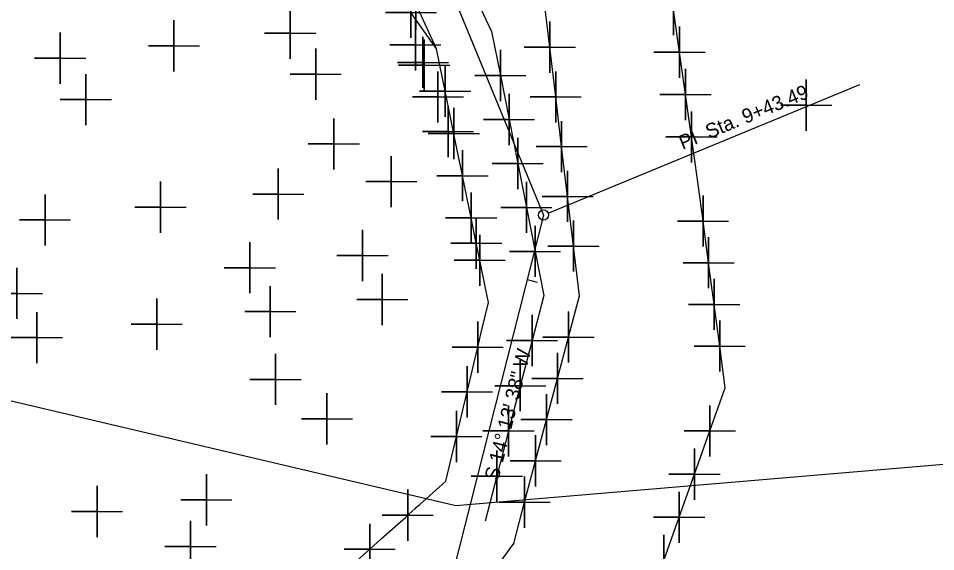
# Model space of a CAD drawing. Extents: x 2260968 to 2264340, y 653057 to 655850.
# Drawn here: x 2261691.8 to 2261781.6, y 654817.2 to 654869.4 of the extents above; entities that cross this region are included whole.
import ezdxf

# ---------------------------------------------------------------- set-up
doc = ezdxf.new("R2010")
doc.units = 0
for name, color, linetype in [('CL_X_Construction', 7, 'Continuous'), ('Default', 7, 'Continuous'), ('GE_X_CL_10', 7, 'Continuous'), ('GK_Patterns2', 7, 'Continuous')]:
    doc.layers.add(name, color=color, linetype=linetype)

msp = doc.modelspace()

# ---------------------------------------------------------------- linework, layer by layer
at = {"layer": 'CL_X_Construction'}
for p, q in [((2261716.474, 654914.987), (2261743.195, 654850.138)), ((2261716.474, 654914.987), (2261743.195, 654850.138)), ((2261743.195, 654850.138), (2261734.002, 654813.881)), ((2261743.195, 654850.138), (2261734.002, 654813.881))]:
    msp.add_line(p, q, dxfattribs=at)
at = {"layer": 'Default'}
for points in [[(2261730.718, 654870.778), (2261730.718, 654873.278), (2261730.718, 654870.778), (2261728.218, 654870.778), (2261730.718, 654870.778), (2261730.718, 654868.278), (2261730.718, 654870.778), (2261733.218, 654870.778)], [(2261730.233, 654869.95), (2261730.233, 654872.45), (2261730.233, 654869.95), (2261727.733, 654869.95), (2261730.233, 654869.95), (2261730.233, 654867.45), (2261730.233, 654869.95), (2261732.733, 654869.95)], [(2261736.009, 654872.552), (2261738.125, 654868.075), (2261738.975, 654863.776), (2261739.825, 654859.477), (2261740.674, 654855.178), (2261741.524, 654850.879), (2261742.374, 654846.58), (2261743.224, 654842.28), (2261742.076, 654837.864), (2261740.928, 654833.448), (2261739.779, 654829.032), (2261738.631, 654824.615), (2261737.483, 654820.199)], [(2261755.909, 654870.203), (2261755.909, 654872.703), (2261755.909, 654870.203), (2261753.409, 654870.203), (2261755.909, 654870.203), (2261755.909, 654867.703), (2261755.909, 654870.203), (2261758.409, 654870.203)], [(2261737.636, 654814.385), (2261740.28, 654818.033), (2261741.351, 654822.068), (2261742.422, 654826.102), (2261743.493, 654830.137), (2261744.564, 654834.171), (2261745.636, 654838.206), (2261746.707, 654842.24), (2261746.128, 654847.1), (2261745.55, 654851.96), (2261744.971, 654856.82), (2261744.393, 654861.68), (2261743.815, 654866.539), (2261743.236, 654871.399)], [(2261718.42, 654867.92), (2261718.42, 654870.42), (2261718.42, 654867.92), (2261715.92, 654867.92), (2261718.42, 654867.92), (2261718.42, 654865.42), (2261718.42, 654867.92), (2261720.92, 654867.92)], [(2261722.48, 654814.139), (2261726.2, 654817.465), (2261727.325, 654818.471), (2261729.197, 654820.144), (2261729.687, 654820.583), (2261729.919, 654820.79), (2261730.017, 654820.878), (2261730.608, 654821.406), (2261730.646, 654821.44), (2261730.67, 654821.462), (2261730.788, 654821.568), (2261731.092, 654821.839), (2261733.638, 654824.116), (2261734.681, 654828.482), (2261735.724, 654832.848), (2261736.767, 654837.214), (2261737.113, 654838.664), (2261737.809, 654841.58), (2261737.521, 654842.99), (2261736.963, 654845.713), (2261736.62, 654847.39), (2261736.62, 654847.39), (2261736.62, 654847.39), (2261736.117, 654849.846), (2261735.271, 654853.979), (2261735.236, 654854.15), (2261734.474, 654857.872), (2261734.425, 654858.112), (2261733.579, 654862.245), (2261732.733, 654866.378), (2261730.718, 654870.778)], [(2261754.959, 654816.366), (2261756.461, 654820.587), (2261757.964, 654824.809), (2261759.466, 654829.03), (2261760.969, 654833.252), (2261760.428, 654837.326), (2261759.888, 654841.4), (2261759.347, 654845.474), (2261758.806, 654849.548), (2261758.266, 654853.621), (2261757.677, 654857.767), (2261757.087, 654861.912), (2261756.498, 654866.057), (2261755.909, 654870.203)], [(2261730.668, 654866.763), (2261730.668, 654869.263), (2261730.668, 654866.763), (2261728.168, 654866.763), (2261730.668, 654866.763), (2261730.668, 654864.263), (2261730.668, 654866.763), (2261733.168, 654866.763)], [(2261732.733, 654866.378), (2261730.233, 654869.95)], [(2261707.05, 654866.68), (2261707.05, 654869.18), (2261707.05, 654866.68), (2261704.55, 654866.68), (2261707.05, 654866.68), (2261707.05, 654864.18), (2261707.05, 654866.68), (2261709.55, 654866.68)], [(2261743.815, 654866.539), (2261743.815, 654869.039), (2261743.815, 654866.539), (2261741.315, 654866.539), (2261743.815, 654866.539), (2261743.815, 654864.039), (2261743.815, 654866.539), (2261746.315, 654866.539)], [(2261756.498, 654866.057), (2261756.498, 654868.557), (2261756.498, 654866.057), (2261753.998, 654866.057), (2261756.498, 654866.057), (2261756.498, 654863.557), (2261756.498, 654866.057), (2261758.998, 654866.057)], [(2261695.93, 654865.47), (2261695.93, 654867.97), (2261695.93, 654865.47), (2261693.43, 654865.47), (2261695.93, 654865.47), (2261695.93, 654862.97), (2261695.93, 654865.47), (2261698.43, 654865.47)], [(2261731.408, 654865.058), (2261731.408, 654867.558), (2261731.408, 654865.058), (2261728.908, 654865.058), (2261731.408, 654865.058), (2261731.408, 654862.558), (2261731.408, 654865.058), (2261733.908, 654865.058)], [(2261731.522, 654864.797), (2261731.522, 654867.297), (2261731.522, 654864.797), (2261729.022, 654864.797), (2261731.522, 654864.797), (2261731.522, 654862.297), (2261731.522, 654864.797), (2261734.022, 654864.797)], [(2261720.92, 654863.91), (2261720.92, 654866.41), (2261720.92, 654863.91), (2261718.42, 654863.91), (2261720.92, 654863.91), (2261720.92, 654861.41), (2261720.92, 654863.91), (2261723.42, 654863.91)], [(2261738.975, 654863.776), (2261738.975, 654866.276), (2261738.975, 654863.776), (2261736.475, 654863.776), (2261738.975, 654863.776), (2261738.975, 654861.276), (2261738.975, 654863.776), (2261741.475, 654863.776)], [(2261733.579, 654862.245), (2261733.579, 654864.745), (2261733.579, 654862.245), (2261731.079, 654862.245), (2261733.579, 654862.245), (2261733.579, 654859.745), (2261733.579, 654862.245), (2261736.079, 654862.245)], [(2261698.44, 654861.42), (2261698.44, 654863.92), (2261698.44, 654861.42), (2261695.94, 654861.42), (2261698.44, 654861.42), (2261698.44, 654858.92), (2261698.44, 654861.42), (2261700.94, 654861.42)], [(2261732.877, 654861.677), (2261732.877, 654864.177), (2261732.877, 654861.677), (2261730.377, 654861.677), (2261732.877, 654861.677), (2261732.877, 654859.177), (2261732.877, 654861.677), (2261735.377, 654861.677)], [(2261744.393, 654861.68), (2261744.393, 654864.18), (2261744.393, 654861.68), (2261741.893, 654861.68), (2261744.393, 654861.68), (2261744.393, 654859.18), (2261744.393, 654861.68), (2261746.893, 654861.68)], [(2261757.087, 654861.912), (2261757.087, 654864.412), (2261757.087, 654861.912), (2261754.587, 654861.912), (2261757.087, 654861.912), (2261757.087, 654859.412), (2261757.087, 654861.912), (2261759.587, 654861.912)], [(2261768.898, 654860.875), (2261768.898, 654863.375), (2261768.898, 654860.875), (2261766.398, 654860.875), (2261768.898, 654860.875), (2261768.898, 654858.375), (2261768.898, 654860.875), (2261771.398, 654860.875)], [(2261739.825, 654859.477), (2261739.825, 654861.977), (2261739.825, 654859.477), (2261737.325, 654859.477), (2261739.825, 654859.477), (2261739.825, 654856.977), (2261739.825, 654859.477), (2261742.325, 654859.477)], [(2261733.86, 654858.29), (2261733.86, 654860.79), (2261733.86, 654858.29), (2261731.36, 654858.29), (2261733.86, 654858.29), (2261733.86, 654855.79), (2261733.86, 654858.29), (2261736.36, 654858.29)], [(2261734.425, 654858.112), (2261734.425, 654860.612), (2261734.425, 654858.112), (2261731.925, 654858.112), (2261734.425, 654858.112), (2261734.425, 654855.612), (2261734.425, 654858.112), (2261736.925, 654858.112)], [(2261757.677, 654857.767), (2261757.677, 654860.267), (2261757.677, 654857.767), (2261755.177, 654857.767), (2261757.677, 654857.767), (2261757.677, 654855.267), (2261757.677, 654857.767), (2261760.177, 654857.767)], [(2261722.69, 654857.08), (2261722.69, 654859.58), (2261722.69, 654857.08), (2261720.19, 654857.08), (2261722.69, 654857.08), (2261722.69, 654854.58), (2261722.69, 654857.08), (2261725.19, 654857.08)], [(2261744.971, 654856.82), (2261744.971, 654859.32), (2261744.971, 654856.82), (2261742.471, 654856.82), (2261744.971, 654856.82), (2261744.971, 654854.32), (2261744.971, 654856.82), (2261747.471, 654856.82)], [(2261740.674, 654855.178), (2261740.674, 654857.678), (2261740.674, 654855.178), (2261738.174, 654855.178), (2261740.674, 654855.178), (2261740.674, 654852.678), (2261740.674, 654855.178), (2261743.174, 654855.178)], [(2261728.31, 654853.4), (2261728.31, 654855.9), (2261728.31, 654853.4), (2261725.81, 654853.4), (2261728.31, 654853.4), (2261728.31, 654850.9), (2261728.31, 654853.4), (2261730.81, 654853.4)], [(2261735.271, 654853.979), (2261735.271, 654856.479), (2261735.271, 654853.979), (2261732.771, 654853.979), (2261735.271, 654853.979), (2261735.271, 654851.479), (2261735.271, 654853.979), (2261737.771, 654853.979)], [(2261717.26, 654852.19), (2261717.26, 654854.69), (2261717.26, 654852.19), (2261714.76, 654852.19), (2261717.26, 654852.19), (2261717.26, 654849.69), (2261717.26, 654852.19), (2261719.76, 654852.19)], [(2261745.55, 654851.96), (2261745.55, 654854.46), (2261745.55, 654851.96), (2261743.05, 654851.96), (2261745.55, 654851.96), (2261745.55, 654849.46), (2261745.55, 654851.96), (2261748.05, 654851.96)], [(2261705.74, 654850.9), (2261705.74, 654853.4), (2261705.74, 654850.9), (2261703.24, 654850.9), (2261705.74, 654850.9), (2261705.74, 654848.4), (2261705.74, 654850.9), (2261708.24, 654850.9)], [(2261741.524, 654850.879), (2261741.524, 654853.379), (2261741.524, 654850.879), (2261739.024, 654850.879), (2261741.524, 654850.879), (2261741.524, 654848.379), (2261741.524, 654850.879), (2261744.024, 654850.879)], [(2261694.45, 654849.65), (2261694.45, 654852.15), (2261694.45, 654849.65), (2261691.95, 654849.65), (2261694.45, 654849.65), (2261694.45, 654847.15), (2261694.45, 654849.65), (2261696.95, 654849.65)], [(2261736.117, 654849.846), (2261736.117, 654852.346), (2261736.117, 654849.846), (2261733.617, 654849.846), (2261736.117, 654849.846), (2261736.117, 654847.346), (2261736.117, 654849.846), (2261738.617, 654849.846)], [(2261758.806, 654849.548), (2261758.806, 654852.048), (2261758.806, 654849.548), (2261756.306, 654849.548), (2261758.806, 654849.548), (2261758.806, 654847.048), (2261758.806, 654849.548), (2261761.306, 654849.548)], [(2261736.62, 654847.39), (2261736.62, 654849.89), (2261736.62, 654847.39), (2261734.12, 654847.39), (2261736.62, 654847.39), (2261736.62, 654844.89), (2261736.62, 654847.39), (2261739.12, 654847.39)], [(2261746.128, 654847.1), (2261746.128, 654849.6), (2261746.128, 654847.1), (2261743.628, 654847.1), (2261746.128, 654847.1), (2261746.128, 654844.6), (2261746.128, 654847.1), (2261748.628, 654847.1)], [(2261725.5, 654846.18), (2261725.5, 654848.68), (2261725.5, 654846.18), (2261723, 654846.18), (2261725.5, 654846.18), (2261725.5, 654843.68), (2261725.5, 654846.18), (2261728, 654846.18)], [(2261742.374, 654846.58), (2261742.374, 654849.08), (2261742.374, 654846.58), (2261739.874, 654846.58), (2261742.374, 654846.58), (2261742.374, 654844.08), (2261742.374, 654846.58), (2261744.874, 654846.58)], [(2261736.963, 654845.713), (2261736.963, 654848.213), (2261736.963, 654845.713), (2261734.463, 654845.713), (2261736.963, 654845.713), (2261736.963, 654843.213), (2261736.963, 654845.713), (2261739.463, 654845.713)], [(2261759.347, 654845.474), (2261759.347, 654847.974), (2261759.347, 654845.474), (2261756.847, 654845.474), (2261759.347, 654845.474), (2261759.347, 654842.974), (2261759.347, 654845.474), (2261761.847, 654845.474)], [(2261714.48, 654844.99), (2261714.48, 654847.49), (2261714.48, 654844.99), (2261711.98, 654844.99), (2261714.48, 654844.99), (2261714.48, 654842.49), (2261714.48, 654844.99), (2261716.98, 654844.99)], [(2261691.69, 654842.48), (2261691.69, 654844.98), (2261691.69, 654842.48), (2261689.19, 654842.48), (2261691.69, 654842.48), (2261691.69, 654839.98), (2261691.69, 654842.48), (2261694.19, 654842.48)], [(2261727.43, 654841.88), (2261727.43, 654844.38), (2261727.43, 654841.88), (2261724.93, 654841.88), (2261727.43, 654841.88), (2261727.43, 654839.38), (2261727.43, 654841.88), (2261729.93, 654841.88)], [(2261716.47, 654840.69), (2261716.47, 654843.19), (2261716.47, 654840.69), (2261713.97, 654840.69), (2261716.47, 654840.69), (2261716.47, 654838.19), (2261716.47, 654840.69), (2261718.97, 654840.69)], [(2261759.888, 654841.4), (2261759.888, 654843.9), (2261759.888, 654841.4), (2261757.388, 654841.4), (2261759.888, 654841.4), (2261759.888, 654838.9), (2261759.888, 654841.4), (2261762.388, 654841.4)], [(2261705.37, 654839.47), (2261705.37, 654841.97), (2261705.37, 654839.47), (2261702.87, 654839.47), (2261705.37, 654839.47), (2261705.37, 654836.97), (2261705.37, 654839.47), (2261707.87, 654839.47)], [(2261693.64, 654838.15), (2261693.64, 654840.65), (2261693.64, 654838.15), (2261691.14, 654838.15), (2261693.64, 654838.15), (2261693.64, 654835.65), (2261693.64, 654838.15), (2261696.14, 654838.15)], [(2261745.636, 654838.206), (2261745.636, 654840.706), (2261745.636, 654838.206), (2261743.136, 654838.206), (2261745.636, 654838.206), (2261745.636, 654835.706), (2261745.636, 654838.206), (2261748.136, 654838.206)], [(2261736.767, 654837.214), (2261736.767, 654839.714), (2261736.767, 654837.214), (2261734.267, 654837.214), (2261736.767, 654837.214), (2261736.767, 654834.714), (2261736.767, 654837.214), (2261739.267, 654837.214)], [(2261742.076, 654837.864), (2261742.076, 654840.364), (2261742.076, 654837.864), (2261739.576, 654837.864), (2261742.076, 654837.864), (2261742.076, 654835.364), (2261742.076, 654837.864), (2261744.576, 654837.864)], [(2261760.428, 654837.326), (2261760.428, 654839.826), (2261760.428, 654837.326), (2261757.928, 654837.326), (2261760.428, 654837.326), (2261760.428, 654834.826), (2261760.428, 654837.326), (2261762.928, 654837.326)], [(2261716.99, 654834.07), (2261716.99, 654836.57), (2261716.99, 654834.07), (2261714.49, 654834.07), (2261716.99, 654834.07), (2261716.99, 654831.57), (2261716.99, 654834.07), (2261719.49, 654834.07)], [(2261744.564, 654834.171), (2261744.564, 654836.671), (2261744.564, 654834.171), (2261742.064, 654834.171), (2261744.564, 654834.171), (2261744.564, 654831.671), (2261744.564, 654834.171), (2261747.064, 654834.171)], [(2261735.724, 654832.848), (2261735.724, 654835.348), (2261735.724, 654832.848), (2261733.224, 654832.848), (2261735.724, 654832.848), (2261735.724, 654830.348), (2261735.724, 654832.848), (2261738.224, 654832.848)], [(2261740.928, 654833.448), (2261740.928, 654835.948), (2261740.928, 654833.448), (2261738.428, 654833.448), (2261740.928, 654833.448), (2261740.928, 654830.948), (2261740.928, 654833.448), (2261743.428, 654833.448)], [(2261722.02, 654830.21), (2261722.02, 654832.71), (2261722.02, 654830.21), (2261719.52, 654830.21), (2261722.02, 654830.21), (2261722.02, 654827.71), (2261722.02, 654830.21), (2261724.52, 654830.21)], [(2261743.493, 654830.137), (2261743.493, 654832.637), (2261743.493, 654830.137), (2261740.993, 654830.137), (2261743.493, 654830.137), (2261743.493, 654827.637), (2261743.493, 654830.137), (2261745.993, 654830.137)], [(2261739.779, 654829.032), (2261739.779, 654831.532), (2261739.779, 654829.032), (2261737.279, 654829.032), (2261739.779, 654829.032), (2261739.779, 654826.532), (2261739.779, 654829.032), (2261742.279, 654829.032)], [(2261759.466, 654829.03), (2261759.466, 654831.53), (2261759.466, 654829.03), (2261756.966, 654829.03), (2261759.466, 654829.03), (2261759.466, 654826.53), (2261759.466, 654829.03), (2261761.966, 654829.03)], [(2261734.681, 654828.482), (2261734.681, 654830.982), (2261734.681, 654828.482), (2261732.181, 654828.482), (2261734.681, 654828.482), (2261734.681, 654825.982), (2261734.681, 654828.482), (2261737.181, 654828.482)], [(2261742.422, 654826.102), (2261742.422, 654828.602), (2261742.422, 654826.102), (2261739.922, 654826.102), (2261742.422, 654826.102), (2261742.422, 654823.602), (2261742.422, 654826.102), (2261744.922, 654826.102)], [(2261738.631, 654824.615), (2261738.631, 654827.115), (2261738.631, 654824.615), (2261736.131, 654824.615), (2261738.631, 654824.615), (2261738.631, 654822.115), (2261738.631, 654824.615), (2261741.131, 654824.615)], [(2261757.964, 654824.809), (2261757.964, 654827.309), (2261757.964, 654824.809), (2261755.464, 654824.809), (2261757.964, 654824.809), (2261757.964, 654822.309), (2261757.964, 654824.809), (2261760.464, 654824.809)], [(2261710.23, 654822.29), (2261710.23, 654824.79), (2261710.23, 654822.29), (2261707.73, 654822.29), (2261710.23, 654822.29), (2261710.23, 654819.79), (2261710.23, 654822.29), (2261712.73, 654822.29)], [(2261741.351, 654822.068), (2261741.351, 654824.568), (2261741.351, 654822.068), (2261738.851, 654822.068), (2261741.351, 654822.068), (2261741.351, 654819.568), (2261741.351, 654822.068), (2261743.851, 654822.068)], [(2261699.53, 654821.16), (2261699.53, 654823.66), (2261699.53, 654821.16), (2261697.03, 654821.16), (2261699.53, 654821.16), (2261699.53, 654818.66), (2261699.53, 654821.16), (2261702.03, 654821.16)], [(2261729.919, 654820.79), (2261729.919, 654823.29), (2261729.919, 654820.79), (2261727.419, 654820.79), (2261729.919, 654820.79), (2261729.919, 654818.29), (2261729.919, 654820.79), (2261732.419, 654820.79)], [(2261756.461, 654820.587), (2261756.461, 654823.087), (2261756.461, 654820.587), (2261753.961, 654820.587), (2261756.461, 654820.587), (2261756.461, 654818.087), (2261756.461, 654820.587), (2261758.961, 654820.587)], [(2261708.67, 654817.73), (2261708.67, 654820.23), (2261708.67, 654817.73), (2261706.17, 654817.73), (2261708.67, 654817.73), (2261708.67, 654815.23), (2261708.67, 654817.73), (2261711.17, 654817.73)], [(2261726.2, 654817.465), (2261726.2, 654819.965), (2261726.2, 654817.465), (2261723.7, 654817.465), (2261726.2, 654817.465), (2261726.2, 654814.965), (2261726.2, 654817.465), (2261728.7, 654817.465)], [(2261754.959, 654816.366), (2261754.959, 654818.866), (2261754.959, 654816.366), (2261752.459, 654816.366), (2261754.959, 654816.366), (2261754.959, 654813.866), (2261754.959, 654816.366), (2261757.459, 654816.366)]]:
    msp.add_lwpolyline(points, dxfattribs=at)
at = {"layer": 'GE_X_CL_10'}
for p, q in [((2261716.474, 654914.987), (2261743.195, 654850.138)), ((2261743.657, 654850.328), (2261774.148, 654862.892)), ((2261743.657, 654850.328), (2261774.148, 654862.892)), ((2261743.195, 654850.138), (2261734.002, 654813.881)), ((2261741.596, 654843.831), (2261742.565, 654843.586)), ((2261741.596, 654843.831), (2261742.565, 654843.586))]:
    msp.add_line(p, q, dxfattribs=at)
msp.add_circle((2261743.195, 654850.138), 0.5, dxfattribs=at)
msp.add_circle((2261743.195, 654850.138), 0.5, dxfattribs=at)
at = {"layer": 'GK_Patterns2'}
msp.add_lwpolyline([(2261636.146, 654844.916), (2261734.619, 654821.73), (2261980.525, 654842.55)], dxfattribs=at)

# ---------------------------------------------------------------- texts
at = {"layer": 'GE_X_CL_10'}
for s, rotation, p in [('PI  Sta. 9+43.49', 22.39418, (2261756.797, 654856.499)), ('PI  Sta. 9+43.49', 22.39418, (2261756.797, 654856.499)), ('S 14%%d 13\' 38" W', 75.77269, (2261738.765, 654824.122))]:
    msp.add_text(s, height=1.4, rotation=rotation, dxfattribs=at).set_placement(p)

doc.saveas('drawing.dxf')
